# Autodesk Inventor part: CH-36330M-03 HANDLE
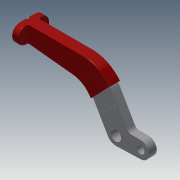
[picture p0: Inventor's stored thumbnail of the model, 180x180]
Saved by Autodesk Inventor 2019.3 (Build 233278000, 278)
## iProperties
Created: 2012-09
Part Number: CH-36330M-03 HANDLE
Material: Ogólny
Document SubType Name: Modeling
Designer: CADENGINEERING4
Density: 1 g/cm^3
Appearance: Domyślna
Author: CADENGINEERING4
Revision Number: ÈÎºÎ
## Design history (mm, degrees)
feature "ÇÐ³ý-À­Éì5"
node "Bryła1"
